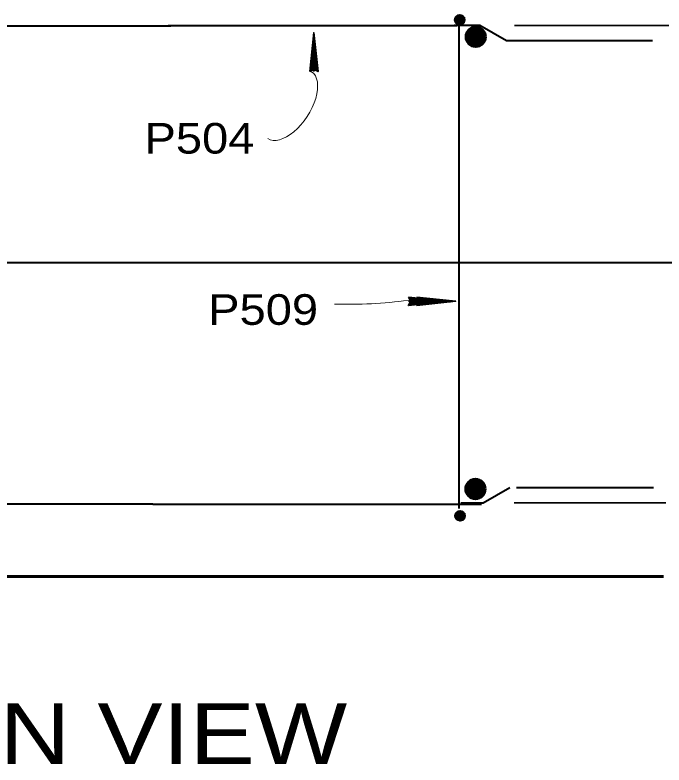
# Model space of a CAD drawing. Extents: x 14.14 to 17.34, y -1.61 to 0.38.
# Drawn here: x 14.8456 to 15.0222, y -0.6274 to -0.4234 of the extents above; entities that cross this region are included whole.
import ezdxf

# ---------------------------------------------------------------- set-up
doc = ezdxf.new("R2010")
doc.units = 0
doc.header["$LTSCALE"] = 0.0033
doc.layers.add('1', color=7, linetype='Continuous', lineweight=40)

msp = doc.modelspace()

# ---------------------------------------------------------------- linework, layer by layer
at = {"layer": '1'}
for p, q in [((14.96575, -0.423917), (14.965667, -0.425417)), ((14.96575, -0.423917), (14.965667, -0.425417)), ((14.965833, -0.423917), (14.96575, -0.425417)), ((14.96575, -0.423917), (14.96775, -0.42425)), ((14.965833, -0.423917), (14.96575, -0.425417)), ((14.96575, -0.423917), (14.96775, -0.42425)), ((14.96575, -0.424), (14.96775, -0.424333)), ((14.96575, -0.424), (14.96775, -0.424333)), ((14.96575, -0.424083), (14.96775, -0.4245)), ((14.96575, -0.424083), (14.96775, -0.4245)), ((14.96575, -0.424167), (14.96775, -0.424583)), ((14.96575, -0.424167), (14.96775, -0.424583)), ((14.96575, -0.424333), (14.967667, -0.424667)), ((14.96575, -0.424333), (14.967667, -0.424667)), ((14.965833, -0.42375), (14.96775, -0.424083)), ((14.965833, -0.42375), (14.96775, -0.424083)), ((14.965917, -0.423917), (14.965833, -0.425417)), ((14.965917, -0.423917), (14.965833, -0.425417)), ((14.966, -0.423917), (14.965917, -0.425417)), ((14.966, -0.423917), (14.965917, -0.425417)), ((14.966083, -0.423917), (14.966, -0.425417)), ((14.966083, -0.423917), (14.966, -0.425417)), ((14.96625, -0.423917), (14.966167, -0.425417)), ((14.96625, -0.423917), (14.966167, -0.425417)), ((14.966333, -0.423917), (14.96625, -0.425417)), ((14.966333, -0.423917), (14.96625, -0.425417)), ((14.966417, -0.423917), (14.966333, -0.425417)), ((14.966417, -0.423917), (14.966333, -0.425417)), ((14.9665, -0.423917), (14.966417, -0.425417)), ((14.9665, -0.423917), (14.966417, -0.425417)), ((14.966583, -0.423917), (14.9665, -0.425417)), ((14.966583, -0.423917), (14.9665, -0.425417)), ((14.966667, -0.423917), (14.966583, -0.425417)), ((14.966667, -0.423917), (14.966583, -0.425417)), ((14.96675, -0.423917), (14.966667, -0.425417)), ((14.96675, -0.423917), (14.966667, -0.425417)), ((14.966917, -0.424), (14.96675, -0.4255)), ((14.966917, -0.424), (14.96675, -0.4255)), ((14.967083, -0.424), (14.966917, -0.4255)), ((14.967083, -0.424), (14.966917, -0.4255)), ((14.967167, -0.424), (14.967083, -0.4255)), ((14.967167, -0.424), (14.967083, -0.4255)), ((14.967167, -0.424), (14.967083, -0.4255)), ((14.967167, -0.424), (14.967083, -0.4255)), ((14.96725, -0.424), (14.967167, -0.4255)), ((14.96725, -0.424), (14.967167, -0.4255)), ((14.967333, -0.424), (14.96725, -0.4255)), ((14.967333, -0.424), (14.96725, -0.4255)), ((14.967417, -0.424), (14.967333, -0.4255)), ((14.967417, -0.424), (14.967333, -0.4255)), ((14.9675, -0.424), (14.967417, -0.4255)), ((14.9675, -0.424), (14.967417, -0.4255)), ((14.967583, -0.424), (14.9675, -0.4255)), ((14.967583, -0.424), (14.9675, -0.4255)), ((14.967667, -0.424), (14.967583, -0.4255)), ((14.967667, -0.424), (14.967583, -0.4255)), ((14.967833, -0.424), (14.96775, -0.4255)), ((14.967833, -0.424), (14.96775, -0.4255)), ((14.88725, -0.42625), (14.965833, -0.42625)), ((14.9655, -0.425333), (14.9675, -0.425667)), ((14.9655, -0.425333), (14.9675, -0.425667)), ((14.965583, -0.424833), (14.967583, -0.42525)), ((14.965583, -0.424833), (14.967583, -0.42525)), ((14.965583, -0.425083), (14.967583, -0.425417)), ((14.965583, -0.425083), (14.967583, -0.425417)), ((14.965583, -0.425167), (14.9675, -0.4255)), ((14.965583, -0.425167), (14.9675, -0.4255)), ((14.965583, -0.42525), (14.9675, -0.425583)), ((14.965583, -0.42525), (14.9675, -0.425583)), ((14.965667, -0.424417), (14.967667, -0.42475)), ((14.965667, -0.424417), (14.967667, -0.42475)), ((14.965667, -0.4245), (14.967667, -0.424917)), ((14.965667, -0.4245), (14.967667, -0.424917)), ((14.965667, -0.424583), (14.967583, -0.425)), ((14.965667, -0.424583), (14.967583, -0.425)), ((14.965667, -0.424667), (14.967583, -0.425083)), ((14.965667, -0.424667), (14.967583, -0.425083)), ((14.966417, -0.42625), (14.966417, -0.557583)), ((14.966417, -0.42625), (14.966417, -0.557583)), ((14.973083, -0.42775), (14.9685, -0.429917)), ((14.968667, -0.428083), (14.969917, -0.426917)), ((14.972667, -0.427417), (14.968833, -0.428083)), ((14.97275, -0.42775), (14.968833, -0.428417)), ((14.97275, -0.427917), (14.968833, -0.428667)), ((14.972833, -0.428167), (14.968917, -0.428917)), ((14.972833, -0.428333), (14.968917, -0.429083)), ((14.97075, -0.42825), (14.969417, -0.42725)), ((14.972833, -0.428583), (14.969, -0.429333)), ((14.972917, -0.42875), (14.969083, -0.429417)), ((14.972917, -0.428917), (14.969083, -0.429667)), ((14.973, -0.429167), (14.969167, -0.429917)), ((14.973, -0.429333), (14.969167, -0.430083)), ((14.973083, -0.429583), (14.969167, -0.430333)), ((14.973167, -0.43), (14.96925, -0.43075)), ((14.973167, -0.430167), (14.969333, -0.430917)), ((14.973167, -0.430417), (14.969333, -0.431083)), ((14.968917, -0.430917), (14.972667, -0.431333)), ((14.97325, -0.4305), (14.969417, -0.43125)), ((14.97325, -0.430667), (14.969417, -0.431417)), ((14.54025, -0.490667), (14.964167, -0.490667)), ((14.964167, -0.490667), (14.98525, -0.490667)), ((14.973, -0.55075), (14.968417, -0.552917)), ((14.968583, -0.551083), (14.969833, -0.549917)), ((14.972583, -0.550417), (14.96875, -0.551083)), ((14.972667, -0.55075), (14.96875, -0.551417)), ((14.970667, -0.55125), (14.969333, -0.55025)), ((14.972667, -0.550917), (14.96875, -0.551667)), ((14.97275, -0.551167), (14.968833, -0.551917)), ((14.97275, -0.551333), (14.968833, -0.552083)), ((14.97275, -0.551583), (14.968917, -0.552333)), ((14.972833, -0.55175), (14.969, -0.552417)), ((14.972833, -0.551917), (14.969, -0.552667)), ((14.972917, -0.552167), (14.969083, -0.552917)), ((14.972917, -0.552333), (14.969083, -0.553083)), ((14.973, -0.552583), (14.969083, -0.553333)), ((15.019417, -0.552), (14.982083, -0.552)), ((14.968833, -0.553917), (14.972583, -0.554333)), ((14.973083, -0.553), (14.969167, -0.55375)), ((14.973083, -0.553167), (14.96925, -0.553917)), ((14.973083, -0.553417), (14.96925, -0.554083)), ((14.973167, -0.5535), (14.969333, -0.55425)), ((14.973167, -0.553667), (14.969333, -0.554417)), ((14.883083, -0.556417), (14.6605, -0.556417)), ((14.883083, -0.556417), (14.972583, -0.556417)), ((14.965833, -0.558833), (14.96575, -0.560333)), ((14.965833, -0.558833), (14.96575, -0.560333)), ((14.965917, -0.558833), (14.965833, -0.560333)), ((14.965833, -0.558833), (14.967833, -0.559167)), ((14.965917, -0.558833), (14.965833, -0.560333)), ((14.965833, -0.558833), (14.967833, -0.559167)), ((14.965833, -0.558917), (14.967833, -0.55925)), ((14.965833, -0.558917), (14.967833, -0.55925)), ((14.965833, -0.559), (14.967833, -0.559417)), ((14.965833, -0.559), (14.967833, -0.559417)), ((14.965917, -0.558667), (14.967833, -0.559)), ((14.965917, -0.558667), (14.967833, -0.559)), ((14.966, -0.558833), (14.965917, -0.560333)), ((14.966, -0.558833), (14.965917, -0.560333)), ((14.966083, -0.558833), (14.966, -0.560333)), ((14.966083, -0.558833), (14.966, -0.560333)), ((14.966167, -0.558833), (14.966083, -0.560333)), ((14.966167, -0.558833), (14.966083, -0.560333)), ((14.966333, -0.558833), (14.96625, -0.560333)), ((14.966333, -0.558833), (14.96625, -0.560333)), ((14.966417, -0.558833), (14.966333, -0.560333)), ((14.966417, -0.558833), (14.966333, -0.560333)), ((14.9665, -0.558833), (14.966417, -0.560333)), ((14.9665, -0.558833), (14.966417, -0.560333)), ((14.966583, -0.558833), (14.9665, -0.560333)), ((14.966583, -0.558833), (14.9665, -0.560333)), ((14.966667, -0.558833), (14.966583, -0.560333)), ((14.966667, -0.558833), (14.966583, -0.560333)), ((14.96675, -0.558833), (14.966667, -0.560333)), ((14.96675, -0.558833), (14.966667, -0.560333)), ((14.966833, -0.558833), (14.96675, -0.560333)), ((14.966833, -0.558833), (14.96675, -0.560333)), ((14.967, -0.558917), (14.966833, -0.560417)), ((14.967, -0.558917), (14.966833, -0.560417)), ((14.967167, -0.558917), (14.967, -0.560417)), ((14.967167, -0.558917), (14.967, -0.560417)), ((14.96725, -0.558917), (14.967167, -0.560417)), ((14.96725, -0.558917), (14.967167, -0.560417)), ((14.96725, -0.558917), (14.967167, -0.560417)), ((14.96725, -0.558917), (14.967167, -0.560417)), ((14.967333, -0.558917), (14.96725, -0.560417)), ((14.967333, -0.558917), (14.96725, -0.560417)), ((14.967417, -0.558917), (14.967333, -0.560417)), ((14.967417, -0.558917), (14.967333, -0.560417)), ((14.9675, -0.558917), (14.967417, -0.560417)), ((14.9675, -0.558917), (14.967417, -0.560417)), ((14.967583, -0.558917), (14.9675, -0.560417)), ((14.967583, -0.558917), (14.9675, -0.560417)), ((14.967667, -0.558917), (14.967583, -0.560417)), ((14.967667, -0.558917), (14.967583, -0.560417)), ((14.96775, -0.558917), (14.967667, -0.560417)), ((14.96775, -0.558917), (14.967667, -0.560417)), ((14.967917, -0.558917), (14.967833, -0.560417)), ((14.967917, -0.558917), (14.967833, -0.560417)), ((14.965583, -0.56025), (14.967583, -0.560583)), ((14.965583, -0.56025), (14.967583, -0.560583)), ((14.965667, -0.55975), (14.967667, -0.560167)), ((14.965667, -0.55975), (14.967667, -0.560167)), ((14.965667, -0.56), (14.967667, -0.560333)), ((14.965667, -0.56), (14.967667, -0.560333)), ((14.965667, -0.560083), (14.967583, -0.560417)), ((14.965667, -0.560083), (14.967583, -0.560417)), ((14.965667, -0.560167), (14.967583, -0.5605)), ((14.965667, -0.560167), (14.967583, -0.5605)), ((14.96575, -0.559333), (14.96775, -0.559667)), ((14.96575, -0.559333), (14.96775, -0.559667)), ((14.96575, -0.559417), (14.96775, -0.559833)), ((14.96575, -0.559417), (14.96775, -0.559833)), ((14.96575, -0.5595), (14.967667, -0.559917)), ((14.96575, -0.5595), (14.967667, -0.559917)), ((14.96575, -0.559583), (14.967667, -0.56)), ((14.96575, -0.559583), (14.967667, -0.56)), ((14.965833, -0.559083), (14.967833, -0.5595)), ((14.965833, -0.559083), (14.967833, -0.5595)), ((14.965833, -0.55925), (14.96775, -0.559583)), ((14.965833, -0.55925), (14.96775, -0.559583))]:
    msp.add_line(p, q, dxfattribs=at)
at = {"layer": '1', "lineweight": 35}
for p, q in [((14.981583, -0.42625), (15.023583, -0.42625)), ((14.926917, -0.43875), (14.926917, -0.428167)), ((14.926917, -0.43875), (14.926917, -0.428167)), ((14.925917, -0.4385), (14.926833, -0.430667)), ((14.925917, -0.4385), (14.926833, -0.430667)), ((14.925917, -0.4385), (14.926833, -0.430667)), ((14.925917, -0.4385), (14.926833, -0.430667)), ((14.926, -0.4385), (14.926833, -0.430667)), ((14.926, -0.4385), (14.926833, -0.430667)), ((14.926083, -0.4385), (14.926917, -0.430667)), ((14.926083, -0.4385), (14.927083, -0.430667)), ((14.926083, -0.4385), (14.926917, -0.430667)), ((14.926083, -0.4385), (14.927083, -0.430667)), ((14.927583, -0.438583), (14.926833, -0.43125)), ((14.927583, -0.438583), (14.926833, -0.43125)), ((14.92775, -0.4385), (14.926917, -0.431167)), ((14.92775, -0.4385), (14.926917, -0.431167)), ((14.927833, -0.4385), (14.927083, -0.431167)), ((14.927833, -0.4385), (14.927083, -0.431167)), ((14.928, -0.4385), (14.927167, -0.431167)), ((14.928, -0.4385), (14.927167, -0.431167)), ((14.952667, -0.50125), (14.96325, -0.50125)), ((14.952667, -0.50125), (14.96325, -0.50125)), ((14.952833, -0.501917), (14.960167, -0.501167)), ((14.952833, -0.501917), (14.960167, -0.501167)), ((14.952917, -0.50025), (14.96075, -0.501167)), ((14.952917, -0.50025), (14.96075, -0.501167)), ((14.952917, -0.50025), (14.96075, -0.501167)), ((14.952917, -0.50025), (14.96075, -0.501167)), ((14.952917, -0.500333), (14.96075, -0.501167)), ((14.952917, -0.500333), (14.96075, -0.501167)), ((14.952917, -0.500417), (14.96075, -0.50125)), ((14.952917, -0.500417), (14.96075, -0.501417)), ((14.952917, -0.500417), (14.96075, -0.50125)), ((14.952917, -0.500417), (14.96075, -0.501417)), ((14.952917, -0.502083), (14.96025, -0.50125)), ((14.952917, -0.502083), (14.96025, -0.50125)), ((14.952917, -0.502167), (14.96025, -0.501417)), ((14.952917, -0.502167), (14.96025, -0.501417)), ((14.952917, -0.502333), (14.96025, -0.5015)), ((14.952917, -0.502333), (14.96025, -0.5015)), ((14.955, -0.50125), (14.965583, -0.50125)), ((14.955, -0.50125), (14.965583, -0.50125)), ((14.955167, -0.501917), (14.9625, -0.501167)), ((14.955167, -0.501917), (14.9625, -0.501167)), ((14.95525, -0.50025), (14.963083, -0.501167)), ((14.95525, -0.50025), (14.963083, -0.501167)), ((14.95525, -0.50025), (14.963083, -0.501167)), ((14.95525, -0.50025), (14.963083, -0.501167)), ((14.95525, -0.500333), (14.963083, -0.501167)), ((14.95525, -0.500333), (14.963083, -0.501167)), ((14.95525, -0.500417), (14.963083, -0.50125)), ((14.95525, -0.500417), (14.963083, -0.501417)), ((14.95525, -0.500417), (14.963083, -0.50125)), ((14.95525, -0.500417), (14.963083, -0.501417)), ((14.95525, -0.502083), (14.962583, -0.50125)), ((14.95525, -0.502083), (14.962583, -0.50125)), ((14.95525, -0.502167), (14.962583, -0.501417)), ((14.95525, -0.502167), (14.962583, -0.501417)), ((14.95525, -0.502333), (14.962583, -0.5015)), ((14.95525, -0.502333), (14.962583, -0.5015)), ((14.9815, -0.556083), (15.02275, -0.556083))]:
    msp.add_line(p, q, dxfattribs=at)
at = {"layer": '1', "lineweight": 60}
for p, q in [((14.9685, -0.429917), (14.968667, -0.428083)), ((14.96875, -0.428), (14.968917, -0.430917)), ((14.969, -0.428), (14.969167, -0.430917)), ((14.969167, -0.428), (14.969417, -0.430917)), ((14.969333, -0.428), (14.9695, -0.430917)), ((14.9695, -0.428), (14.96975, -0.430917)), ((14.96975, -0.427917), (14.969917, -0.430833)), ((14.969833, -0.427917), (14.97, -0.430833)), ((14.97, -0.427917), (14.970167, -0.430833)), ((14.970083, -0.427917), (14.97025, -0.430833)), ((14.97025, -0.427917), (14.9705, -0.430833)), ((14.9705, -0.427917), (14.97075, -0.430833)), ((14.97075, -0.427833), (14.970917, -0.43075)), ((14.970917, -0.427833), (14.971167, -0.43075)), ((14.971167, -0.427833), (14.971333, -0.43075)), ((14.971333, -0.427833), (14.9715, -0.43075)), ((14.9715, -0.427833), (14.971667, -0.43075)), ((14.971583, -0.42775), (14.971833, -0.43075)), ((14.971833, -0.42775), (14.972, -0.43075)), ((14.972083, -0.42775), (14.97225, -0.43075)), ((14.97225, -0.42775), (14.9725, -0.43075)), ((14.972417, -0.42775), (14.972583, -0.43075)), ((14.972583, -0.42775), (14.972833, -0.430667)), ((14.972833, -0.42775), (14.973, -0.430667)), ((14.9685, -0.429917), (14.97325, -0.430667)), ((14.970667, -0.550833), (14.970833, -0.55375)), ((14.970833, -0.550833), (14.971083, -0.55375)), ((14.971083, -0.550833), (14.97125, -0.55375)), ((14.97125, -0.550833), (14.971417, -0.55375)), ((14.971417, -0.550833), (14.971583, -0.55375)), ((14.9715, -0.55075), (14.97175, -0.55375)), ((14.97175, -0.55075), (14.971917, -0.55375)), ((14.972, -0.55075), (14.972167, -0.55375)), ((14.972167, -0.55075), (14.972417, -0.55375)), ((14.972333, -0.55075), (14.9725, -0.55375)), ((14.9725, -0.55075), (14.97275, -0.553667)), ((14.97275, -0.55075), (14.972917, -0.553667)), ((14.968417, -0.552917), (14.968583, -0.551083)), ((14.968667, -0.551), (14.968833, -0.553917)), ((14.968917, -0.551), (14.969083, -0.553917)), ((14.969083, -0.551), (14.969333, -0.553917)), ((14.96925, -0.551), (14.969417, -0.553917)), ((14.969417, -0.551), (14.969667, -0.553917)), ((14.969667, -0.550917), (14.969833, -0.553833)), ((14.96975, -0.550917), (14.969917, -0.553833)), ((14.969917, -0.550917), (14.970083, -0.553833)), ((14.97, -0.550917), (14.970167, -0.553833)), ((14.970167, -0.550917), (14.970417, -0.553833)), ((14.970417, -0.550917), (14.970667, -0.553833)), ((14.968417, -0.552917), (14.973167, -0.553667)), ((14.979333, -0.576083), (14.665583, -0.576083)), ((15.022083, -0.576083), (14.882333, -0.576083))]:
    msp.add_line(p, q, dxfattribs=at)
at = {"layer": '1'}
for points in [[(14.965333, -0.42475), (14.967917, -0.424417), (14.965583, -0.423917), (14.967917, -0.425), (14.9655, -0.425417), (14.9675, -0.42575), (14.9675, -0.423667), (14.966583, -0.426), (14.966833, -0.423417), (14.965833, -0.42575), (14.966167, -0.423417), (14.967, -0.426), (14.965417, -0.42425), (14.967833, -0.424083), (14.966167, -0.425917), (14.96725, -0.4235), (14.965583, -0.423917), (14.9655, -0.425417), (14.966583, -0.426), (14.9675, -0.42575), (14.967917, -0.425), (14.967833, -0.424083), (14.96725, -0.4235), (14.966583, -0.424583), (14.96775, -0.4255), (14.965833, -0.42575), (14.966583, -0.424583), (14.9655, -0.424083), (14.9665, -0.423417), (14.966583, -0.4245), (14.967417, -0.42575), (14.965417, -0.4245), (14.96675, -0.424167), (14.9675, -0.423667)], [(14.9655, -0.425417), (14.966583, -0.426), (14.9675, -0.42575), (14.967917, -0.425), (14.967833, -0.424083), (14.96725, -0.4235), (14.966583, -0.424583), (14.96775, -0.4255), (14.965833, -0.42575), (14.966583, -0.424583), (14.9655, -0.424083), (14.9665, -0.423417), (14.966583, -0.4245), (14.967417, -0.42575), (14.965417, -0.4245), (14.96675, -0.424167), (14.9675, -0.423667)], [(14.967917, -0.424417), (14.965583, -0.423917), (14.967917, -0.425)], [(14.610417, -0.4305), (14.650917, -0.4305), (14.658167, -0.426333), (14.888, -0.426333)], [(15.019083, -0.430417), (14.979333, -0.430417), (14.972083, -0.42625), (14.965167, -0.42625)], [(14.97325, -0.430667), (14.971167, -0.431917), (14.969417, -0.431417), (14.9685, -0.429917)], [(14.885583, -0.490667), (14.964167, -0.490667), (15.088167, -0.490667)], [(14.98025, -0.552), (14.973, -0.556167), (14.966917, -0.556167)], [(14.973167, -0.553667), (14.971083, -0.554917), (14.969333, -0.554417), (14.968417, -0.552917)], [(14.965417, -0.559667), (14.968, -0.559333), (14.965667, -0.558833), (14.968, -0.559917), (14.965583, -0.560333), (14.967583, -0.560667), (14.967583, -0.558583), (14.966667, -0.560917), (14.966917, -0.558333), (14.965917, -0.560667), (14.96625, -0.558333), (14.967083, -0.560917), (14.9655, -0.559167), (14.967917, -0.559), (14.96625, -0.560833), (14.967333, -0.558417), (14.965667, -0.558833), (14.965583, -0.560333), (14.966667, -0.560917), (14.967583, -0.560667), (14.968, -0.559917), (14.967917, -0.559), (14.967333, -0.558417), (14.966667, -0.5595), (14.967833, -0.560417), (14.965917, -0.560667), (14.966667, -0.5595), (14.965583, -0.559), (14.966583, -0.558333), (14.966667, -0.559417), (14.9675, -0.560667), (14.9655, -0.559417), (14.966833, -0.559083), (14.967583, -0.558583)], [(14.965417, -0.559667), (14.968, -0.559333), (14.965667, -0.558833), (14.968, -0.559917), (14.965583, -0.560333), (14.967583, -0.560667), (14.967583, -0.558583), (14.966667, -0.560917), (14.966917, -0.558333), (14.965917, -0.560667), (14.96625, -0.558333), (14.967083, -0.560917), (14.9655, -0.559167), (14.967917, -0.559), (14.96625, -0.560833), (14.967333, -0.558417), (14.965667, -0.558833), (14.965583, -0.560333), (14.966667, -0.560917), (14.967583, -0.560667), (14.968, -0.559917), (14.967917, -0.559), (14.967333, -0.558417), (14.966667, -0.5595), (14.967833, -0.560417), (14.965917, -0.560667), (14.966667, -0.5595), (14.965583, -0.559), (14.966583, -0.558333), (14.966667, -0.559417), (14.9675, -0.560667), (14.9655, -0.559417), (14.966833, -0.559083), (14.967583, -0.558583)]]:
    msp.add_lwpolyline(points, dxfattribs=at)
msp.add_lwpolyline([(14.9655, -0.425417), (14.9675, -0.42575), (14.9675, -0.423667), (14.966583, -0.426), (14.966833, -0.423417), (14.965833, -0.42575), (14.966167, -0.423417), (14.967, -0.426), (14.965417, -0.42425), (14.967833, -0.424083), (14.966167, -0.425917), (14.96725, -0.4235), (14.965583, -0.423917)], close=True, dxfattribs=at)
at = {"layer": '1', "lineweight": 35}
for points in [[(14.925833, -0.43875), (14.926917, -0.428167), (14.928083, -0.43875), (14.926917, -0.438167)], [(14.925833, -0.43875), (14.926917, -0.428167), (14.928083, -0.43875), (14.926917, -0.438167)], [(14.926833, -0.438), (14.92675, -0.433333), (14.926833, -0.433333), (14.926833, -0.43425), (14.92675, -0.438), (14.926667, -0.435), (14.926583, -0.438167), (14.9265, -0.435917), (14.926417, -0.438167), (14.926667, -0.434667), (14.926833, -0.43), (14.927083, -0.430917), (14.927083, -0.429667), (14.927083, -0.438), (14.92725, -0.435583), (14.92725, -0.438167), (14.926833, -0.432833), (14.9275, -0.438167)], [(14.926833, -0.438), (14.92675, -0.433333), (14.926833, -0.433333), (14.926833, -0.43425), (14.92675, -0.438), (14.926667, -0.435), (14.926583, -0.438167), (14.9265, -0.435917), (14.926417, -0.438167), (14.926667, -0.434667), (14.926833, -0.43), (14.927083, -0.430917), (14.927083, -0.429667), (14.927083, -0.438), (14.92725, -0.435583), (14.92725, -0.438167), (14.926833, -0.432833), (14.9275, -0.438167)], [(14.952667, -0.500167), (14.96325, -0.50125), (14.952667, -0.502417), (14.95325, -0.50125)], [(14.952667, -0.500167), (14.96325, -0.50125), (14.952667, -0.502417), (14.95325, -0.50125)], [(14.953417, -0.501167), (14.958083, -0.501083), (14.958083, -0.501167), (14.957167, -0.501167), (14.953417, -0.501083), (14.956417, -0.501), (14.95325, -0.500917), (14.9555, -0.500833), (14.95325, -0.50075), (14.95675, -0.501), (14.961417, -0.501167), (14.9605, -0.501417), (14.96175, -0.501417), (14.953417, -0.501417), (14.955833, -0.501583), (14.95325, -0.501583), (14.958583, -0.501167), (14.95325, -0.501833)], [(14.953417, -0.501167), (14.958083, -0.501083), (14.958083, -0.501167), (14.957167, -0.501167), (14.953417, -0.501083), (14.956417, -0.501), (14.95325, -0.500917), (14.9555, -0.500833), (14.95325, -0.50075), (14.95675, -0.501), (14.961417, -0.501167), (14.9605, -0.501417), (14.96175, -0.501417), (14.953417, -0.501417), (14.955833, -0.501583), (14.95325, -0.501583), (14.958583, -0.501167), (14.95325, -0.501833)], [(14.955, -0.500167), (14.965583, -0.50125), (14.955, -0.502417), (14.955583, -0.50125)], [(14.955, -0.500167), (14.965583, -0.50125), (14.955, -0.502417), (14.955583, -0.50125)], [(14.95575, -0.501167), (14.960417, -0.501083), (14.960417, -0.501167), (14.9595, -0.501167), (14.95575, -0.501083), (14.95875, -0.501), (14.955583, -0.500917), (14.957833, -0.500833), (14.955583, -0.50075), (14.959083, -0.501), (14.96375, -0.501167), (14.962833, -0.501417), (14.964083, -0.501417), (14.95575, -0.501417), (14.958167, -0.501583), (14.955583, -0.501583), (14.960917, -0.501167), (14.955583, -0.501833)], [(14.95575, -0.501167), (14.960417, -0.501083), (14.960417, -0.501167), (14.9595, -0.501167), (14.95575, -0.501083), (14.95875, -0.501), (14.955583, -0.500917), (14.957833, -0.500833), (14.955583, -0.50075), (14.959083, -0.501), (14.96375, -0.501167), (14.962833, -0.501417), (14.964083, -0.501417), (14.95575, -0.501417), (14.958167, -0.501583), (14.955583, -0.501583), (14.960917, -0.501167), (14.955583, -0.501833)]]:
    msp.add_lwpolyline(points, close=True, dxfattribs=at)
at = {"layer": '1', "lineweight": 60}
for points in [[(14.973667, -0.429417), (14.9685, -0.42875), (14.973083, -0.42775)], [(14.969417, -0.431417), (14.969417, -0.42725), (14.971083, -0.431917), (14.970583, -0.42675), (14.972667, -0.431333), (14.971917, -0.426833), (14.970333, -0.431833), (14.9735, -0.4285), (14.968667, -0.428083), (14.971917, -0.43175), (14.969917, -0.426917), (14.973083, -0.42775), (14.97325, -0.430667)], [(14.969917, -0.426917), (14.971167, -0.429083), (14.968917, -0.430917)], [(14.972667, -0.431333), (14.971167, -0.429083), (14.973333, -0.428167), (14.971333, -0.42675), (14.971167, -0.429), (14.9695, -0.431333), (14.9735, -0.429), (14.97075, -0.42825)], [(14.973583, -0.552417), (14.968417, -0.55175), (14.973, -0.55075)], [(14.969333, -0.554417), (14.969333, -0.55025), (14.971, -0.554917), (14.9705, -0.54975), (14.972583, -0.554333), (14.971833, -0.549833), (14.97025, -0.554833), (14.973417, -0.5515), (14.968583, -0.551083), (14.971833, -0.55475), (14.969833, -0.549917), (14.973, -0.55075), (14.973167, -0.553667)], [(14.969833, -0.549917), (14.971083, -0.552083), (14.968833, -0.553917)], [(14.972583, -0.554333), (14.971083, -0.552083), (14.97325, -0.551167), (14.97125, -0.54975), (14.971083, -0.552), (14.969417, -0.554333), (14.973417, -0.552), (14.970667, -0.55125)]]:
    msp.add_lwpolyline(points, dxfattribs=at)
at = {"layer": '1', "lineweight": 35}
for points in [[(14.926833, -0.438), (14.926083, -0.438417), (14.926333, -0.438167), (14.926667, -0.438), (14.926583, -0.43775), (14.92625, -0.437917), (14.927, -0.438083), (14.9275, -0.43825), (14.927917, -0.4385)], [(14.926833, -0.438), (14.926083, -0.438417), (14.926333, -0.438167), (14.926667, -0.438), (14.926583, -0.43775), (14.92625, -0.437917), (14.927, -0.438083), (14.9275, -0.43825), (14.927917, -0.4385)], [(14.953417, -0.501167), (14.953, -0.500417), (14.95325, -0.500667), (14.953417, -0.501), (14.953667, -0.500917), (14.9535, -0.500583), (14.953333, -0.501333), (14.953167, -0.501833), (14.952917, -0.50225)], [(14.953417, -0.501167), (14.953, -0.500417), (14.95325, -0.500667), (14.953417, -0.501), (14.953667, -0.500917), (14.9535, -0.500583), (14.953333, -0.501333), (14.953167, -0.501833), (14.952917, -0.50225)], [(14.95575, -0.501167), (14.955333, -0.500417), (14.955583, -0.500667), (14.95575, -0.501), (14.956, -0.500917), (14.955833, -0.500583), (14.955667, -0.501333), (14.9555, -0.501833), (14.95525, -0.50225)], [(14.95575, -0.501167), (14.955333, -0.500417), (14.955583, -0.500667), (14.95575, -0.501), (14.956, -0.500917), (14.955833, -0.500583), (14.955667, -0.501333), (14.9555, -0.501833), (14.95525, -0.50225)]]:
    msp.add_lwpolyline(points, dxfattribs=at)
at = {"layer": '1'}
for centre in [(14.966667, -0.4247), (14.96675, -0.559617), (14.96675, -0.559617)]:
    msp.add_circle(centre, 0.00132, dxfattribs=at)
at = {"layer": '1', "lineweight": 60}
for centre in [(14.971, -0.429317), (14.970917, -0.552317)]:
    msp.add_circle(centre, 0.00264, dxfattribs=at)
at = {"layer": '1', "lineweight": 13}
msp.add_arc((14.93659, -0.381636), 0.120431, 268.09338, 277.63143, dxfattribs=at)
msp.add_arc((14.93659, -0.381636), 0.120431, 268.09338, 277.63143, dxfattribs=at)
msp.add_ellipse((14.920375, -0.447917), major_axis=(-0.005958, -0.009083), ratio=0.519389, start_param=6.2831853, end_param=9.424778, dxfattribs=at)

# ---------------------------------------------------------------- texts
at = {"layer": '1'}
for s, height, width, p in [('P504', 0.008334, 1.15, (14.880833, -0.461083)), ('P509', 0.008334, 1.15, (14.898167, -0.507667)), ('P509', 0.008334, 1.15, (14.898167, -0.507667)), ('STEM PLAN VIEW', 0.01658, 1.2, (14.709833, -0.627167))]:
    msp.add_text(s, height=height, dxfattribs=dict(at, width=width)).set_placement(p)

doc.saveas('drawing.dxf')
